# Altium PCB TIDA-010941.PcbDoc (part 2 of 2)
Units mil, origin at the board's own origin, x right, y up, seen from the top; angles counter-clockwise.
Board outline 3700 x 3700 mil, 4 copper layers (Top Layer, POWER, GROUND RETURN, Bottom Layer), stack 60.134 mil thick; 115 components, 62 nets, 289 pads, 271 vias.
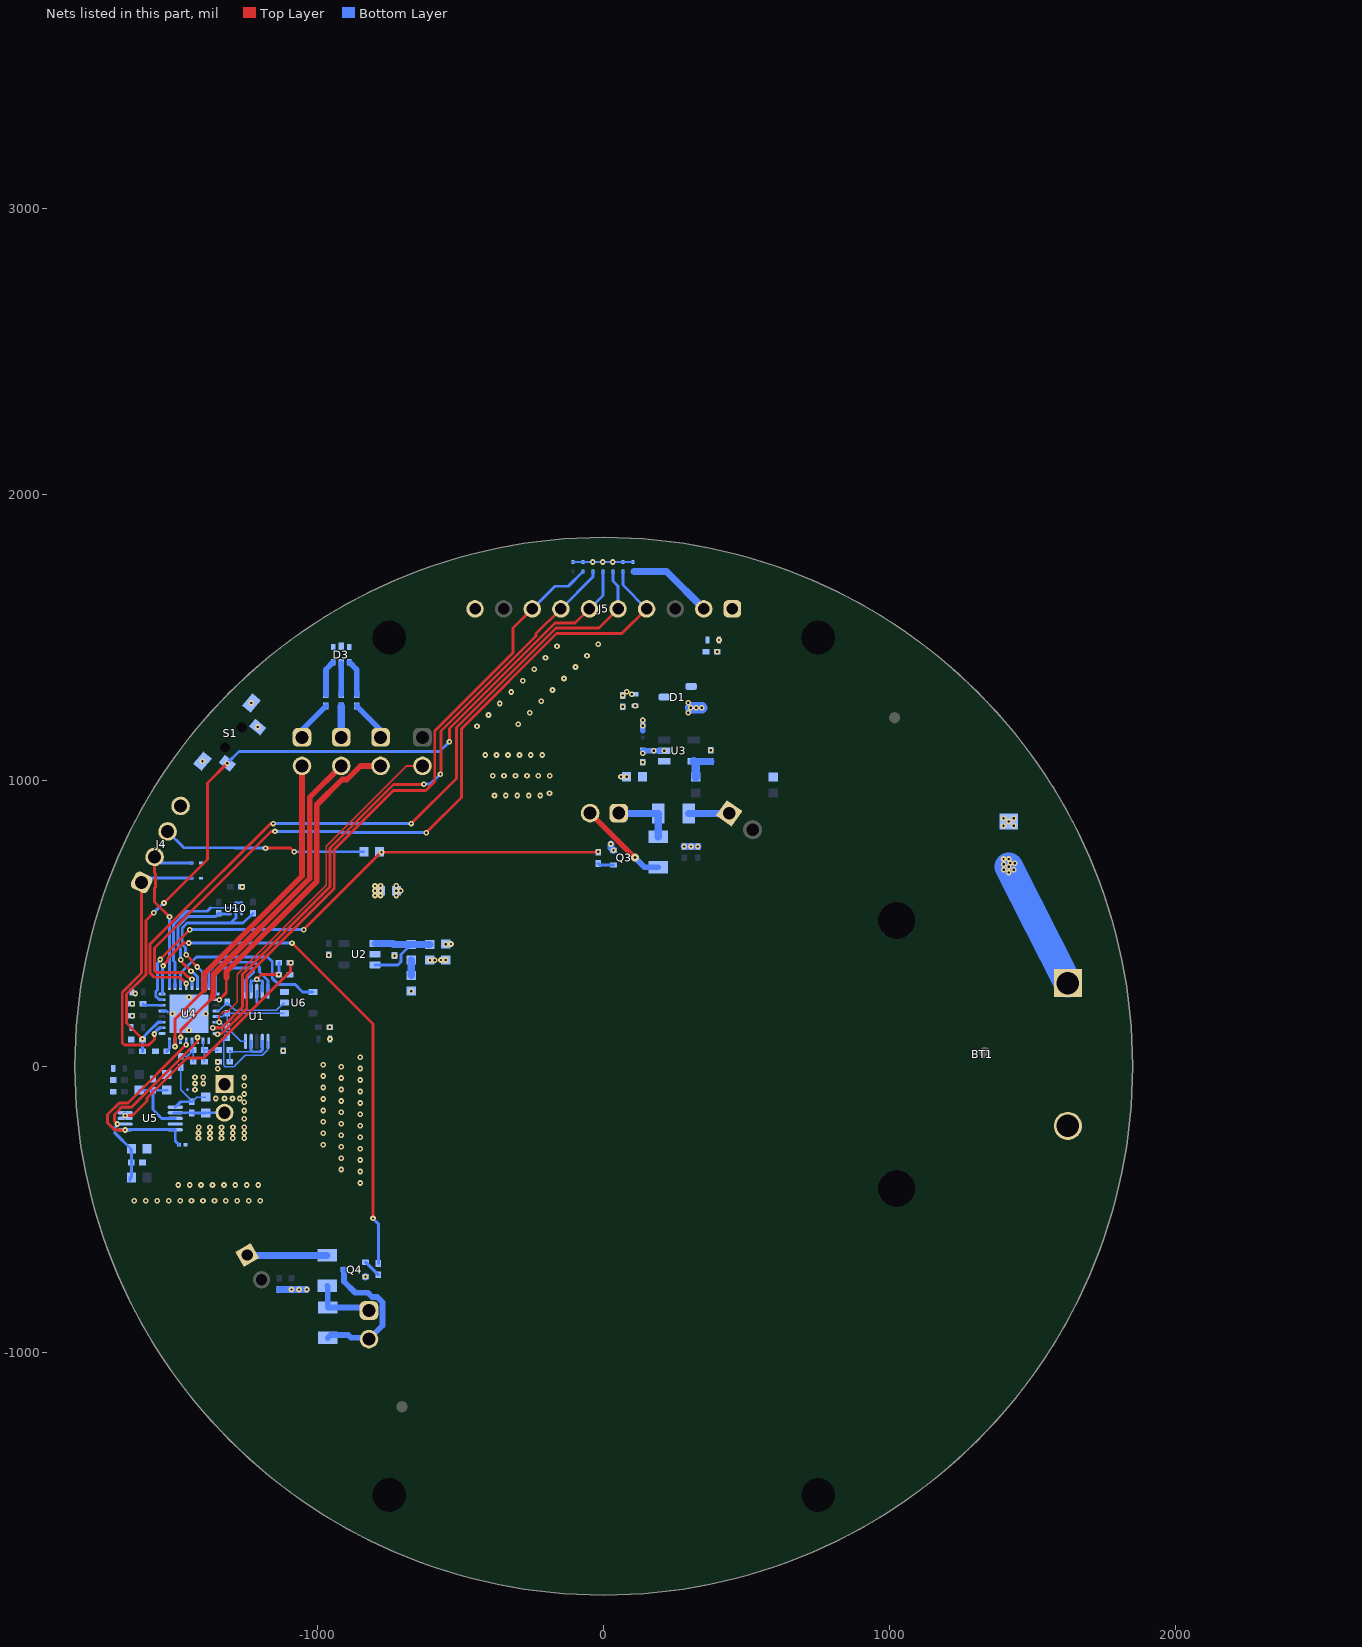
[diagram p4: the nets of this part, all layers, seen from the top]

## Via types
v1: diameter 20, hole 8, Top Layer to Bottom Layer, tented both sides, 215 vias
v2: diameter 19.68, hole 7.87, Top Layer to Bottom Layer, 48 vias
v3: diameter 20, hole 8, Top Layer to Bottom Layer, 7 vias
v4: diameter 28, hole 10, Top Layer to Bottom Layer, tented both sides, 1 vias

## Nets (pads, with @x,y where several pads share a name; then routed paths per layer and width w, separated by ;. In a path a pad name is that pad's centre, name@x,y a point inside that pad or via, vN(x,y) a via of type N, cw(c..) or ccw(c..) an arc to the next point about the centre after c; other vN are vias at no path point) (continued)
GND: C5.2 C8.2 C11.1 C12.2 C13.2 C14.2 C15.2 C16.2 C17.2 C18.2 C19.2 C21.2 C22.2 C24.1 C27.2 C30.2 C34.2 D2.1 D3.1 D3.2 D3.3 D15.2 D16.2 J4.4 J5.10 R8.1 R9.1 R11.2 R16.2 R21.2 S1.1 S1.2 S1.4 U1.3 U2.2 U4.5 U4.25 U4.33 U5.4 U6.3 U10.B1 U10.C1 | length 81.7
  Bottom Layer w10: U4.5@-1545.02,193.57 -1529.51,193.57 -1525.37,189.43 ; -1456.19,-82.19 -1456.19,-81.61 ; U10.B1@-1286.73,572.08 U10.C1@-1267.04,572.08 ; U1.3@-1213.89,262.47 -1213.55,262.12 -1213.55,223.1 -1213.19,222.74
  other v1: -1641.8,-470.14 -1601.8,-470.14 -1561.8,-470.14 -1521.8,-470.14 -1481.8,-470.14 -1441.8,-470.14 -1401.8,-470.14 -1361.8,-470.14 -1321.8,-470.14 -1281.8,-470.14 -1241.8,-470.14 -1201.8,-470.14 -1488.49,-415.02 -1448.49,-415.02 -1408.49,-415.02 -1368.49,-415.02 -1328.49,-415.02 -1288.49,-415.02 -1248.49,-415.02 -1208.49,-415.02 -851.96,-408.16 -851.96,-368.16 -917.96,-361.3 -851.96,-328.16 -917.96,-321.3 -851.96,-288.16 -917.96,-281.3 -981.16,-274.44 -1417.24,-251.62 -1377.24,-251.62 -1337.24,-251.62 -1297.24,-251.62 -1257.24,-251.62 -851.96,-248.16 -917.96,-241.3 -981.16,-234.44 -1417.2,-233.27 -1377.2,-233.27 -1337.2,-233.27 -1297.2,-233.27 -1257.24,-233.27 -1417,-213.03 -1377,-213.03 -1337,-213.03 -1297,-213.03 -1257,-213.03 -851.96,-208.16 -917.96,-201.3 -981.16,-194.44 -1257,-184.07 -851.96,-168.16 -917.96,-161.3 -1257,-155.1 -981.16,-154.44 -851.96,-128.16 -1257,-126.14 -917.96,-121.3 -981.16,-114.44 -1356.71,-112.46 -1326.5,-112.46 -1298.37,-112.46 -1273.35,-112.46 -1257,-97.17 -851.96,-88.16 -1429.84,-82.25 -917.96,-81.3 -981.16,-74.44 -1257,-68.21 -1429.84,-60.54 -1401.16,-60.54 -851.96,-48.16 -917.96,-41.3 -1429.84,-38.89 -1257,-39.24 -1401.32,-38.64 -981.16,-34.44 -1349.79,-8.86 -851.96,-8.16 -917.96,-1.3 -981.16,5.56 -1349.81,15.17 -851.96,31.84 -1121.29,53.89 -957.57,95.52 -958.75,136.04 -1649.11,176.75 -1649.11,218.26 -1638.98,254.22 -962.01,388.05 -800.24,597.53 -780.56,597.53 -800.24,614.26 -780.56,614.26 -1264.91,627.28 -800.24,630.63 -382.48,946.86 -342.48,946.86 -302.48,946.86 -262.48,946.86 -222.48,946.86 -190,955 -388.68,1016.12 -348.68,1016.12 -308.68,1016.12 -268.68,1016.12 -228.68,1016.12 -188.68,1016.12 -1403.31,1066.94 -414.91,1088.78 -374.91,1088.78 -334.91,1088.78 -294.91,1088.78 -254.91,1088.78 -214.91,1088.78 -1210.47,1186.51 -443.39,1188.87 -298.93,1196.32 -403.39,1228.87 -258.93,1236.32 -363.39,1268.87 -1232.49,1270.52 -218.93,1276.32 -323.39,1308.87 -178.93,1316.32 -283.39,1348.87 -138.93,1356.32 -243.39,1388.87 -98.93,1396.32 -203.39,1428.87 -58.93,1436.32 -163.39,1468.87 -18.93,1476.32
  other v2: -1450.54,125.66 -1508.61,183.73 -1450.54,183.73 -1392.47,183.73 -1450.54,241.8
  other v3: -780.56,630.99
GND_5V: BT1.2 C3.1 C4.1 C6.1 C7.1 C23.2 C25.2 C26.2 C31.2 C32.2 C33.1 C35.2 C36.1 C37.2 D6.1 D8.2 D9.2 D10.2 D11.2 D12.2 D13.2 D14.2 J5.1 Q3.2 Q4.2 R16.1 R24.2 R25.1 U3.2 | length 494.3
  Bottom Layer w6: D13.2@-109.36,1763.54 D10.2@-3,1763.54 D14.2@103.36,1763.54
  Bottom Layer w20: C26.2@136.04,1102.81 137.2,1103.97 v1(211.91,1103.97) ; R24.2@136.04,1174.07 v1(136.04,1210)
  Bottom Layer w25: C6.1@-1134.48,-780.69 v1(-1092.09,-780.69) v1(-1039.26,-780.69) ; Q4.2@-833.49,-736.52 v2(-833.49,-736.34) ; v1(24.98,777.56) 24.98,764.3 v1(34.17,755.11) ; v1(281.32,768.89) v1(328.99,768.89)
  other v1: -1065.67,-780.69 -673.28,262.83 -731.95,387.01 -552.59,426.93 -533.91,427.43 -725.44,597.53 -725.44,614.26 -709.69,614.26 -725.44,630.99 305.16,768.89 1398.61,841.68 1434.53,841.68 1417,856.33 1398.61,867.55 1434.53,867.55 60.69,1013.08 80.38,1013.08 136.04,1094.94 174.55,1103.97 374.65,1105.18 136.04,1191.35 66.57,1257.58 109.96,1261.26 397.43,1450 403.21,1491 -38.01,1763.54 -3,1763.73 32.01,1763.73
HDC_INT: U4.10 U10.C2 | length 490.6
  Bottom Layer w5: -1374.52,554.65 -1288.98,554.65 U10.C2@-1267.04,532.71
  Bottom Layer w10: U4.10@-1499.75,278.22 -1499.75,364.38 -1504.43,369.07 -1504.43,496.19 -1458.54,542.09 -1387.08,542.09 -1374.52,554.65
HDC_SCL: R12.2 U4.15 U10.B2 | length 545
  Top Layer w10: v2(-1460.71,390.41) -1440.72,370.42 -1440.72,366 v2(-1421.82,347.11)
  Bottom Layer w10: v2(-1460.71,390.41) -1462.57,392.27 -1462.57,414.56 -1474.43,426.43 -1474.43,483.76 -1457.66,500.54 -1305.69,500.54 ; v2(-1421.82,347.11) -1420.84,347.11 -1401.32,327.59 U4.15@-1401.32,278.22 ; U10.B2@-1286.73,532.71 -1286.73,519.5 -1305.69,500.54 ; R12.2@-1227.03,534.81 -1261.31,500.54 -1305.69,500.54
HDC_SDA: R13.2 U4.14 U10.A2 | length 444.9
  Top Layer w10: v2(-1480,372.7) -1480,368.89 v2(-1443.65,332.54)
  Bottom Layer w10: v2(-1480,372.7) -1480.56,373.25 -1480.56,411.34 -1489.43,420.21 -1489.43,489.98 -1456.15,523.26 -1358.12,523.26 R13.2@-1346.42,534.96 -1344.16,532.71 U10.A2@-1306.41,532.71 ; v2(-1443.65,332.54) -1441.79,330.69 -1438.91,330.69 -1420.38,312.15 -1420.38,295.72 -1420.93,295.17 -1420.93,278.3 U4.14@-1421.01,278.22
I_TIA_IN: C1.2 D2.2 R2.2 U5.2 | length 179.3
  Bottom Layer w5: R2.2@-1392.96,-163.36 R2.2@-1392.28,-162.67 R2.2@-1391.33,-161.72
  Bottom Layer w10: U5.2@-1504.09,-162.77 -1441.26,-162.77 C1.2@-1440.67,-163.36 R2.2@-1392.96,-163.36 ; R2.2@-1392.07,-162.46 D2.2@-1326.5,-162.46
INT_RST_T1C0: U4.11 U6.4 | length 619.6
  Bottom Layer w10: U4.11@-1480.06,278.22 -1480.06,284.95 -1480.22,285.11 -1480.22,326.24 -1423.96,382.5 -1175.57,382.5 -1159.37,366.29 -1159.37,307.8 -1138.15,286.58 -1079.65,286.58 -1053.22,260.14 U6.4@-1016.95,260.14
LED_BLUE_MOD_T2C1: R23.2 U4.8 | length 1834.6
  Top Layer w10: v2(-1541.3,351.06) -1541.3,353.62 -1525.01,369.9 -1525.01,376.97 -1470.63,431.35 v2(-1451.3,431.35) ; v2(-1090.41,430.86) -973.12,313.58 -972.81,313.58 -806.91,147.68 v2(-806.91,-532.2)
  Bottom Layer w10: U4.8@-1543.15,252.71 -1543.15,349.2 v2(-1541.3,351.06) ; v2(-1451.3,431.35) v2@-1090.88,431.33 ; v2(-806.91,-532.2) -788.49,-550.62 R23.2@-788.49,-690.04
LED_DEMOD_T0_N: U1.1 U4.17 | length 306.3
  Bottom Layer w10: U4.17@-1356.05,252.63 -1357.83,254.41 -1357.83,328.07 -1342.18,343.72 -1229.96,343.72 -1224.11,337.86 -1224.11,329.57 -1252.92,300.76 -1252.92,262.82 U1.1@-1253.26,262.47
LED_DEMOD_T0_P: U1.5 U4.16 | length 348
  Bottom Layer w10: U4.16@-1381.64,278.22 -1381.64,332.54 -1350.46,363.72 -1221.68,363.72 -1204.11,346.14 -1204.11,329.27 -1174.87,300.03 -1174.87,262.82 U1.5@-1174.52,262.47
LED_IR_MOD_T2C0: R22.2 R26.2 U4.7 | length 1854.6
  Top Layer w10: v2(-1551.7,373.63) v2@-1450.25,475.08 ; v2(-1049.7,477.62) -778.83,748.48 v3(-777.22,748.48) -21.44,748.48 v2(-19.49,750.43)
  Bottom Layer w10: v2(-1551.7,373.63) -1551.7,371.01 -1561.14,361.57 -1561.14,266.23 -1566.84,260.54 -1566.84,244.72 -1555.06,232.94 U4.7@-1545.02,232.94 ; v2(-1447.71,477.62) -1447.16,478.16 -1050.24,478.16 v2(-1049.7,477.62) ; R26.2@-784.11,750.13 -778.87,750.13 v3(-777.22,748.48)
NetC27_1: C27.1 R5.1 R8.2 U5.3 | length 255.2
  Bottom Layer w10: R5.1@-1624.93,-83.84 -1577.03,-83.84 C27.1@-1576.54,-84.33 ; R8.2@-1527.91,-83.84 -1576.04,-83.84 C27.1@-1576.54,-84.33 ; U5.3@-1498.83,-182.35 -1545.91,-182.35 -1576.54,-151.72 C27.1@-1576.54,-84.33
NetC38_1: C38.1 R25.2 | length 53.3
  Bottom Layer w25: R25.2@-673.28,317.95 C38.1@-673.28,371.27
NetD3_4: D3.4 R20.1 | length 123.7
  Bottom Layer w20: R20.1@-971.85,1299.71 -971.85,1387.75 D3.4@-946.65,1412.94
NetD3_5: D3.5 R18.2 | length 110.3
  Bottom Layer w20: R18.2@-918.11,1299.71 D3.5@-918.11,1409.99
NetD3_6: D3.6 R19.2 | length 123.7
  Bottom Layer w20: D3.6@-889.57,1412.94 -864.37,1387.75 R19.2@-864.37,1299.71
NetD4_1: D4.1 R6.1 | length 142.1
  Bottom Layer w25: R6.1@297.1,884.57 R6.1@296.95,884.42 438.39,884.42 D4.1@438.68,884.72
NetD5_1: D5.1 R10.1 | length 280.2
  Bottom Layer w25: D5.1@-1246.93,-660.1 -1245.33,-661.7 R10.1@-967.43,-661.7
NetJ1_1: J1.1 R19.1 | length 144.3
  Bottom Layer w20: R19.1@-864.37,1260.34 -780.72,1176.7 J1.1@-780.72,1150.65
NetJ2_1: J2.1 R18.1 | length 109.7
  Bottom Layer w25: J2.1@-918.11,1150.65 R18.1@-918.11,1260.34
NetJ3_1: J3.1 R20.2 | length 144.3
  Bottom Layer w20: J3.1@-1055.5,1150.65 -1055.5,1176.7 R20.2@-971.85,1260.34
NetJ4_3: J4.3 R26.1 | length 716
  Top Layer w10: v3(-1183.47,762.9) -1095.67,762.9 v3(-1082.9,750.13)
  Bottom Layer w10: J4.3@-1525.74,821.4 -1468.6,764.26 -1289.16,764.26 -1288.9,764 -1184.57,764 v3(-1183.47,762.9) ; v3(-1082.9,750.13) R26.1@-839.23,750.13
NetJ7_1: J7.1 R6.2 R27.1 | length 220.8
  Bottom Layer w25: J7.1@52.47,885.42 53.47,884.42 R6.2@190.65,884.42 190.65,802.52 R27.1@190.85,802.33
NetJ7_2: J7.2 Q3.3 R27.2 | length 319.6
  Top Layer w20: J7.2@-45.07,885.42 J7.2@-47.53,885.42 107.29,730.6 v4(109.75,730.6)
  Bottom Layer w20: Q3.3@108.98,729.52 142.47,696.03 R27.2@190.85,696.03
NetJ8_1: J8.1 R10.2 R28.1 | length 225.1
  Bottom Layer w20: R10.2@-967.43,-768 -965.07,-770.36 R28.1@-965.07,-843.85 -831.78,-843.85 J8.1@-821.22,-854.41
NetJ8_2: J8.2 Q4.3 R28.2 | length 509.7
  Bottom Layer w20: R28.2@-965.07,-950.15 -954.84,-939.93 -893.7,-939.93 -883.7,-949.93 -825.7,-949.93 J8.2@-821.22,-954.41 -773.74,-906.93 -773.74,-825.23 -792.04,-806.93 -810.07,-806.93 -824.55,-792.45 -869.17,-792.45 -908.29,-753.33 Q4.3@-908.29,-710.93
NetQ3_1: Q3.1 R22.1 | length 55.8
  Bottom Layer w10: R22.1@-19.49,709.11 -14.31,703.93 Q3.1@34.17,703.93
NetQ4_1: Q4.1 R23.1 | length 63.2
  Bottom Layer w10: Q4.1@-833.49,-685.34 -832.56,-685.34 R23.1@-788.49,-729.41
NetR4_2: R4.2 U1.6 | length 314
  Bottom Layer w5: R4.2@-1316.76,100.53 -1328.76,88.52 -1328.76,69.85 -1328.53,69.62 -1328.53,3.66 -1328.16,3.29 -1327.78,3.29 -1327.78,2.22 -1323.39,-2.18 -1293.55,-2.18 -1289.16,2.22 -1289.16,3.47 -1254.43,38.2 -1194.15,38.2 -1174.52,57.83 U1.6@-1174.52,87.27
NetR29_2: R29.2 U5.8 U5.9 | length 845.4
  Top Layer w10: v2(-1674.03,-172.51) -1648.36,-172.51 -1597.37,-121.53 -1597.37,-110.64 -1457.79,28.95 -1399.35,28.95 -1095.09,333.21 v2(-1095.09,362.14)
  Bottom Layer w10: U5.8@-1674.03,-182.35 v2(-1674.03,-172.51) U5.9@-1674.03,-162.67 ; R29.2@-1097.03,362.14 v2(-1095.09,362.14)
OPA0_IN0-: C2.2 C10.2 R1.2 U4.28 | length 126.5
  Bottom Layer w5: C10.2@-1479.51,35.02 -1457.69,35.02 R1.2@-1436.04,56.67 -1440.69,61.33 U4.28@-1440.69,89.24 ; C2.2@-1436.04,15.17 R1.2@-1436.04,54.7
OPA0_OUT: C2.1 R1.1 R3.2 U4.26 | length 124.8
  Bottom Layer w5: U4.26@-1401.32,89.24 -1401.32,61.33 R1.1@-1396.67,56.67 ; C2.1@-1396.67,15.17 R1.1@-1396.67,56.67 ; R3.2@-1347.84,56.67 R1.1@-1396.67,56.67
OPA1_IN0+: J6.2 U1.10 U4.22 | length 1373.2
  Top Layer w6: v2(-1344.58,154.2) -1345.67,155.3 -1345.67,176.05 -1330.89,190.83 -1316.15,190.83 -1282.14,224.84 -1282.14,321.69 -970.72,633.12 -970.72,769.38 -689.45,1050.65 J6.2@-634,1050.65
  Bottom Layer w5: v2@-1342.02,154.2 -1334.1,146.28 -1334.1,124.98 -1329.7,120.59 -1303.81,120.59 -1270.49,87.27 U1.10@-1253.26,87.27
  Bottom Layer w10: U4.22@-1356.05,154.2 v2(-1344.58,154.2)
OPA1_IN0-: C9.1 R4.1 U4.21 U6.1 | length 282.2
  Bottom Layer w5: U4.21@-1356.05,173.89 -1334.93,173.89 C9.1@-1323.48,185.34 ; R4.1@-1316.76,139.9 C9.1@-1316.76,185.34 U6.1@-1117.35,185.34
OPA1_OUT: C9.2 U4.20 U6.2 | length 273.5
  Bottom Layer w5: U4.20@-1356.05,193.57 -1345.92,193.57 -1316.76,222.74 -1289.35,195.34 -1144.75,195.34 U6.2@-1117.35,222.74
PA19_SWDIO: D11.1 J5.7 U4.23 | length 2262
  Top Layer w10: v2(-1367.78,134.49) -1367.65,134.36 -1336.36,134.36 -1263.58,207.14 -1263.58,321.87 -957.72,627.73 -957.72,764 -735.62,986.09 v2(-629.07,986.09) ; v2(-571.37,1021.76) -569.32,1023.81 -569.32,1172.9 -236.77,1505.46 -236.77,1513.23 J5.7@-150,1600
  Bottom Layer w10: v2(-1367.78,134.49) -1369.83,132.44 -1369.83,129.75 -1360.81,129.75 U4.23@-1356.05,134.52 ; v2(-629.07,986.09) -627.22,987.95 -605.19,987.95 v2(-571.37,1021.76) ; J5.7@-150,1600 -38.01,1711.99 D11.1@-38.01,1730.46
PA20_SWCLK: D12.1 J5.8 U4.24 | length 2256.7
  Top Layer w10: v2(-1351.24,112.37) -1349.38,114.23 -1335.28,114.23 -1248.58,200.93 -1248.58,315.66 -942.72,621.52 -942.72,757.79 -736.24,964.26 -622.84,964.26 -591.21,995.89 -591.21,1172.22 -317,1446.43 -317,1533 J5.8@-250,1600
  Bottom Layer w10: U4.24@-1356.05,114.83 -1351.32,114.83 -1351.24,114.75 v2(-1351.24,112.37) ; J5.8@-250,1600 -170.77,1679.23 -124.26,1679.23 D12.1@-73.03,1730.46
PA.0: U4.1
PA.1: D15.1 J4.1 U4.2 | length 952.4
  Top Layer w10: J4.1@-1616.54,643.2 -1616.54,326.16 -1684.11,258.59 -1684.11,81.43 -1676.57,73.9 -1591.76,73.9 -1571.68,93.98 v2(-1571.68,112.82)
  Bottom Layer w10: J4.1@-1616.54,643.2 -1601.79,657.94 D15.1@-1441.32,657.94 ; v2(-1571.68,112.82) -1566.84,117.66 -1566.84,122.74 -1559.82,129.75 -1554.74,129.75 -1549.98,134.52 U4.2@-1545.02,134.52
PA.5: D16.1 J4.2 U4.9 | length 616.5
  Top Layer w10: J4.2@-1571.14,732.3 -1571.14,675.78 -1568.46,673.09 -1568.46,625.22 -1571.14,622.53 -1571.14,574.65 v3(-1519.25,522.76)
  Bottom Layer w10: J4.2@-1571.14,732.3 -1549.94,711.1 D16.1@-1441.32,711.1 ; U4.9@-1519.43,278.22 -1519.43,522.58 v3(-1519.25,522.76)
PA.14: J1.2 U4.18 | length 1109.4
  Top Layer w10: v2(-1344.58,232.94) -1320.51,257.01 -1320.51,309.26 -1319.28,310.5
  Top Layer w20: -1319.28,310.5 -1319.28,331.23 -1003.72,646.79 -1003.72,914.56 -915.1,1003.17 -898.44,1003.17 -850.96,1050.65 J1.2@-780.72,1050.65
  Bottom Layer w6: v2@-1345.68,239.71 -1344.58,238.61 v2(-1344.58,232.94)
PA.26: J2.2 U4.30 | length 1194.9
  Top Layer w10: v2(-1480.04,100.97) -1479.43,101.58 -1479.43,125.82 -1427.58,177.67 -1427.58,181.25 -1370.73,238.1 -1369.42,238.1
  Top Layer w20: -1369.42,238.1 -1369.42,243.23 -1366.02,246.64 -1366.02,319.84 -1028.72,657.14 -1028.72,940.04 J2.2@-918.11,1050.65
  Bottom Layer w10: U4.30@-1480.05,89.26 v2(-1480.04,100.97)
PA.27: J3.2 U4.31 | length 1188
  Top Layer w10: -1499.88,109.19 -1499.88,98.84 -1502,96.72 -1499.51,94.23 v2(-1499.51,69) ; -1499.75,109.32 -1499.75,164.53 -1397.29,266.98 -1396.98,266.98
  Top Layer w20: -1396.98,266.98 -1396.98,324.24 -1055.5,665.72 J3.2@-1055.5,1050.65
  Bottom Layer w10: U4.31@-1499.75,89.24 U4.31@-1499.75,89.24 -1499.67,69.16 v2(-1499.51,69)
R\S\T\: C34.1 D10.1 J5.6 R17.2 S1.3 U4.3 | length 2945.2
  Top Layer w10: v2(-1613.57,95.26) -1669.11,150.8 -1669.11,252.37 -1601.54,319.94 -1601.54,509.95 -1574.71,536.78 v3(-1573.89,536.78) ; v3(-1538.22,571.14) -1385.58,723.78 -1385.58,991.02 v2(-1316.76,1059.84) ; v2(-539.8,1134.88) -539.8,1181.21 -171.01,1550 -100,1550 J5.6@-50,1600
  Bottom Layer w10: R17.2@-1613.57,52.23 -1613.57,89.8 -1611.6,91.77 -1611.6,100.96 -1591.3,121.26 ; -1590.23,122.33 -1558.36,154.2 U4.3@-1545.02,154.2 ; v3(-1573.89,536.78) -1539.53,571.14 v3(-1538.22,571.14) ; v2(-1316.76,1059.84) -1275.95,1100.65 -574.03,1100.65 v2(-539.8,1134.88) ; J5.6@-54.4,1604.4 J5.6@-50,1600 -3,1647 D10.1@-3,1730.46
ROSC: R11.1 U4.6 | length 69.1
  Bottom Layer w10: R11.1@-1612.04,218.26 -1607.04,213.26 U4.6@-1545.02,213.26
S\H\D\N\_\T\I\A\: R21.1 U4.29 U5.5 U5.6 | length 725.2
  Top Layer w10: v2(-1674.25,-222.79) -1710.6,-222.66 -1735.76,-197.5 -1735.76,-169.32 -1694.44,-128 -1664.01,-128 v2(-1460.84,75.17)
  Bottom Layer w6: v2(-1460.84,75.17) -1460.38,75.63 U4.29@-1460.38,89.24
  Bottom Layer w10: v2(-1674.25,-222.79) -1674.25,-221.94 U5.6@-1674.03,-221.72 U5.5@-1498.83,-221.72 -1498.83,-261.07 R21.1@-1485.46,-274.44
TARGET_RXD: D8.1 J5.4 U4.13 | length 2764.9
  Top Layer w10: v2(-1440.22,303.94) -1442.84,303.94 -1451.6,312.7 -1454.83,312.7 -1470.2,328.07 -1565.68,328.07 -1571.54,333.93 -1571.54,413.79 -1163.93,821.4 v2(-1149.74,821.4) ; v2(-620.67,817.19) -497.86,940 -497.86,1180.72 -165.35,1513.23 63.23,1513.23 J5.4@150,1600
  Bottom Layer w10: U4.13@-1440.62,285.03 -1440.54,285.11 -1440.54,303.62 v2(-1440.22,303.94) ; v2(-1149.74,821.4) -922.87,821.4 -918.67,817.19 v2(-620.67,817.19) ; D8.1@67.03,1730.46 67.03,1682.97 J5.4@150,1600
TARGET_TXD: D9.1 J5.5 U4.12 | length 2607.3
  Top Layer w10: v2(-1460.38,289.69) -1481.96,311.27 -1572.44,311.27 -1586.54,325.37 -1586.54,427.32 -1511.1,502.76 -1510.97,502.76 -1499.25,514.48 -1499.25,514.61 -1165.05,848.82 v2(-1156.07,848.82) ; v2(-673.28,848.82) -515,1007.1 -515,1184.8 -166.8,1533 -17,1533 J5.5@50,1600
  Bottom Layer w10: v2(-1156.07,848.82) v2(-673.28,848.82) ; D9.1@32.01,1730.46 32.01,1697.23 50,1679.23 J5.5@50,1600
VBAT_9V0: BT1.1 D1.2 D6.2 | length 494.2
  Bottom Layer w40: v1(304.23,1253.93) v1(342.58,1253.93)
  Bottom Layer w100: v1(1417,697.67) BT1.1@1623.43,291.18
  other v1: 1417,677.79 1399.47,687.73 1434.53,687.72 1399.47,706.97 1437.87,709.87 1421.61,710.95 1398.61,725.23 1417,725.23 296,1236.18 323.4,1253.93 296,1271.71
VCORE: C21.1 U4.32 | length 40.9
  Bottom Layer w10: C21.1@-1528.76,52.23 -1519.43,61.56 U4.32@-1519.43,89.24
VeREF+: C12.1 R7.1 R9.2 U4.27 U5.7 | length 686.6
  Top Layer w10: v2(-1701.25,-202.04) -1710.91,-192.38 -1710.91,-168.87 -1685.04,-143 -1650.95,-143 -1421.01,86.94 v2(-1421.01,100.71)
  Bottom Layer w10: U5.7@-1699.38,-203.91 -1710.6,-215.14 -1710.6,-232.31 -1652.18,-290.74 -1655.56,-294.12 -1652.18,-297.5 R7.1@-1652.18,-389 ; R7.1@-1657.6,-399.76 R7.1@-1657.6,-389 ; U4.27@-1421.01,89.24 -1421.31,88.94 -1421.31,100.41 v2(-1421.01,100.71)
VIN_LDO: C26.1 C31.1 C32.1 C33.2 C37.1 D1.3 L1.2 U3.1
  other v1: -607.88,370.77 -591.14,371.27 -569.32,371.82 -552.59,371.32 136.04,1063.44 66.57,1296.95 97.96,1301.26 80.35,1309.62
VIN_LDO33: C23.1 C38.2 L1.1 U2.1 U2.3 | length 365.2
  Bottom Layer w10: U2.3@-800.39,354.58 -720.15,354.58 -708.93,365.81 -708.93,390.74 C38.2@-673.28,426.38
  Bottom Layer w25: U2.1@-800.39,429.39 -734.95,429.39 C23.1@-731.95,426.38 C38.2@-673.28,426.38 L1.1@-607.88,426.38
VLP_5V0: C35.1 C36.2 D1.1 D14.1 J5.2 R14.2 | length 297.1
  Bottom Layer w25: 106.95,1730.46 219.54,1730.46 J5.2@350,1600
VLPF: C11.2 R3.1 U1.7 U1.9 | length 229.2
  Bottom Layer w5: C11.2@-1308.47,15.17 -1308.72,15.41 -1308.47,15.66 R3.1@-1308.47,56.67 -1302.5,50.7 -1228.98,50.7
  Bottom Layer w10: U1.9@-1233.58,87.27 -1233.58,55.3 -1228.98,50.7 -1201.5,50.7 -1194.21,57.99 U1.7@-1194.21,87.27
VOUT_LDO50: C25.1 R15.2 U3.5 | length 118.9
  Bottom Layer w25: U3.5@314.28,1066.57 373.89,1066.57 C25.1@374.65,1065.81
  Bottom Layer w30: U3.5@314.28,1066.57 321.93,1058.92 R15.2@321.93,1011.56
VREF_LPF: C19.1 R29.1 U1.2 U1.4 | length 247.3
  Top Layer w10: v2(-1213.69,303.89) -1196.94,320.63 v2(-1136.4,320.63)
  Bottom Layer w10: U1.2@-1233.58,262.47 -1233.58,298.89 -1220.64,298.89 -1220.48,299.05 -1213.89,299.05 v2@-1213.74,299.2 ; U1.4@-1194.21,262.47 -1194.21,298.16 -1194.94,298.89 -1207.15,298.89 -1207.31,299.05 -1213.74,299.05 v2@-1213.74,299.2 ; v2(-1136.4,320.63) R29.1@-1136.4,362.14 ; v2@-1213.74,299.2 -1213.74,303.84 v2(-1213.69,303.89) -1213.69,299.25 v2@-1213.74,299.2
VTIA_OUT: C1.1 C10.1 R2.1 U5.1 | length 257
  Bottom Layer w5: C10.1@-1479.51,-4.35 -1479.51,-82.33 -1448.01,-113.83 -1448.01,-116.64 C1.1@-1440.67,-123.99 -1424.23,-107.55 R2.1@-1392.28,-107.55
  Bottom Layer w10: U5.1@-1498.83,-142.98 -1479.83,-123.99 C1.1@-1440.67,-123.99
pads on no net: BT1.MH1 BT1.MH2 FID1.1 FID2.1 FID3.1 H1. H2. H3. H4. J5.3 LBL1.0 S1. U2.4 U3.4

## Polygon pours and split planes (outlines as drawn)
GND on POWER "GND_GUARDRING" (solid, pour order 44): -1588.95,-97.94 -1540.99,-97.94 -1544.82,-97.94 -1544.82,-86.2 -1543.49,-84.87 -1543.49,-38.64 -1538.22,-33.36 -1516.16,-33.36 -1515.19,-32.39 -1509.91,-32.39 -1484.01,-6.49 -1459.66,-6.49 -1457.85,-4.68 -1374.86,-4.68 -1374.86,31.62 -1369.65,36.83 -1334.53,36.83 -1332.71,35.01 -1330.28,35.01 -1330.28,-4.68 -1286.66,-4.68 -1286.66,98.12 -1282.14,102.64 -1257.91,102.64 -1257.9,51.01 -1240.03,33.14 -1240.03,-36.31 -1240.03,-84.87 -1240.03,-148.3 -1240.03,-326.96 -1588.95,-326.96
5V0 on POWER "POWER-5V0" (solid, remove dead copper, pour order 59): -1897,-1989 858,-1989 858,973.8 267.91,973.8 267.91,57 -745.73,57 -745.73,-560 -1897,-560
VBAT_9V0 on POWER "POWER_VBAT_9V0_P058" (solid, remove dead copper, pour order 58): -554,1821 -565.17,1809.83 -565.17,1677.41 267.31,1677.41 267.31,993.94 870.06,993.94 882,982 880.53,980.53 880.53,-1813 893,-1813 1814,-892 1814,1788 1781,1821
VIN_LDO on POWER "POWER_VIN_LDO_P043" (solid, remove dead copper, pour order 43): 41.14,1340.19 250,1340.19 250,70 -745.73,70 -745.73,693.36 -34.36,693.36 -34.36,1099.25 41.14,1099.25 162.95,1099.25 162.95,1155.94 41.14,1155.94
3V3 on POWER "POWER_3V3_P053" (solid, pour order 53): -1508.68,-538.49 -761.64,-538.49 -761.64,712.1 -49.52,712.1 -49.52,1111.49 155.88,1111.49 155.88,1153.87 28.42,1153.87 28.42,1353.38 213.32,1353.38 213.32,1665 -676.46,1665 -744.22,1624.06 -788,1606.39 -883.59,1567.82 -976.3,1516.23 -1112.91,1412.99 -1210.08,1330.1 -1735.76,804.43 -1735.76,523.26 -1777.02,482 -1778.02,483 -1780.02,483 -1780.02,474.77 -1828.02,426.77 -1828.02,-319 -1710.64,-538.49
GND_5V on GROUND RETURN "GROUND_RETURN_GND_5V_P040" (solid, remove dead copper, pour order 40): -620.67,1667 215.95,1667 215.95,1340.19 41.14,1340.19 41.14,1155.94 162.95,1155.94 162.95,1099.29 -34.36,1099.29 -34.36,693.36 -748.24,693.36 -748.24,-560 -1699.95,-560 -1950,-560 -875.43,-2068 565.85,-2068 1808,-914 1808,1794 1794,1808 -607,1808 -620.67,1733 -677.23,1667.74
GND on GROUND RETURN "GROUND_RETURN_GND_P055" (solid, pour order 55): -1508.68,-538.49 -761.64,-538.49 -761.64,712.1 -49.52,712.1 -49.52,1111.49 155.88,1111.49 155.88,1153.87 28.42,1153.87 28.42,1353.38 213.32,1353.38 213.32,1665 -676.46,1665 -744.22,1624.06 -788,1606.39 -883.59,1567.82 -976.3,1516.23 -1112.91,1412.99 -1210.08,1330.1 -1735.76,804.43 -1735.76,523.26 -1777.02,482 -1778.02,483 -1780.02,483 -1780.02,474.77 -1828.02,426.77 -1828.02,-319 -1710.64,-538.49
GND on GROUND RETURN "GND_GUARDRING" (solid, pour order 51): -1588.95,-97.94 -1540.99,-97.94 -1544.82,-97.94 -1544.82,-86.2 -1543.49,-84.87 -1543.49,-38.64 -1538.22,-33.36 -1516.16,-33.36 -1515.19,-32.39 -1509.91,-32.39 -1484.01,-6.49 -1459.66,-6.49 -1457.85,-4.68 -1374.86,-4.68 -1374.86,31.62 -1369.65,36.83 -1334.53,36.83 -1332.71,35.01 -1330.28,35.01 -1330.28,-4.68 -1286.66,-4.68 -1286.66,98.12 -1282.14,102.64 -1257.91,102.64 -1257.9,51.01 -1240.03,33.14 -1240.03,-36.31 -1240.03,-84.87 -1240.03,-148.3 -1240.03,-326.96 -1517.4,-326.96 -1588.95,-326.96
5V0 on Bottom Layer "Bottom Layer-5V0" (solid, remove dead copper, pour order 60): -1793,-1854 858,-1854 858,974.53 250,974.53 250,57 -745.73,57 -745.73,-560 -1793,-560
VIN_LDO on Bottom Layer "BOTTOM_LAYER_VIN_LDO_P057" (solid, remove dead copper, pour order 57): 40.96,1340.74 266.56,1340.74 266.56,70.56 -745.92,70.56 -745.92,693.92 -34.55,693.92 -34.55,1099.81 40.96,1099.81 162.77,1099.81 162.77,1155.94 40.96,1155.94
GND on Bottom Layer "BOTTOM_LAYER_GND_P056" (solid, pour order 56): -1508.68,-538.49 -761.64,-538.49 -761.64,712.1 -49.52,712.1 -49.52,1111.49 155.88,1111.49 155.88,1153.87 28.42,1153.87 28.42,1353.38 213.32,1353.38 213.32,1665 -1002.67,1665 -1778.02,1003.57 -1778.02,483 -1780.02,483 -1780.02,474.77 -1828.02,426.77 -1828.02,-519.6 -1817.92,-538.49
GND on Bottom Layer "GND_GUARDRING" (solid, pour order 32): -1588.95,-97.94 -1540.99,-97.94 -1544.82,-97.94 -1544.82,-86.2 -1543.49,-84.87 -1543.49,-38.64 -1538.22,-33.36 -1516.16,-33.36 -1515.19,-32.39 -1509.91,-32.39 -1484.01,-6.49 -1459.66,-6.49 -1457.85,-4.68 -1374.86,-4.68 -1374.86,31.62 -1369.65,36.83 -1334.53,36.83 -1332.71,35.01 -1330.28,35.01 -1330.28,-4.68 -1286.66,-4.68 -1286.66,98.12 -1282.14,102.64 -1257.91,102.64 -1257.9,51.01 -1240.03,33.14 -1240.03,-36.31 -1240.03,-84.87 -1240.03,-148.3 -1240.03,-326.96 -1517.4,-326.96 -1588.95,-326.96
VLP_5V0 on Bottom Layer "VLP_5V0_bot" (solid, remove dead copper, pour order 28): 857,984 267.31,984 267.31,1000 267.31,1681.09 -777.24,1681.09 -777.24,1795.14 857.1,1795.14 857,1792.98
GND on Top Layer "GND_GUARDRING" (solid, pour order 52): -1588.95,-97.94 -1540.99,-97.94 -1544.82,-97.94 -1544.82,-86.2 -1543.49,-84.87 -1543.49,-38.64 -1538.22,-33.36 -1516.16,-33.36 -1515.19,-32.39 -1509.91,-32.39 -1484.01,-6.49 -1459.66,-6.49 -1457.85,-4.68 -1374.86,-4.68 -1374.86,31.62 -1369.65,36.83 -1334.53,36.83 -1332.71,35.01 -1330.28,35.01 -1330.28,-4.68 -1286.66,-4.68 -1286.66,98.12 -1282.14,102.64 -1257.91,102.64 -1257.9,51.01 -1240.03,33.14 -1240.03,-36.31 -1240.03,-84.87 -1240.03,-148.3 -1240.03,-326.96 -1517.4,-326.96 -1588.95,-326.96

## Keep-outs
Keep-Out Layer:
  text ".Layer_Name" at -1161.91,-2932.68 h60

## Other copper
Top Layer:
  pour cut-out: -1467.9,-146.76 -1435.9,-146.76 -1415.9,-146.76 -1414.08,-142.58 -1357.64,-142.58 -1340.94,-125.89 -1337.43,-125.89 -1314.23,-125.89 -1310.71,-125.89 -1299.69,-136.9 -1291.82,-148.3 -1289.33,-150.78 -1289.33,-177.5 -1291.82,-179.99 -1310.71,-198.88 -1314.23,-198.88 -1337.43,-198.88 -1340.94,-198.88 -1355.74,-184.08 -1370.61,-184.08 -1414.08,-184.08 -1417.33,-180.83 -1439.68,-180.83 -1455.58,-180.83 -1470.55,-180.83 -1475.02,-185.3 -1475.02,-188.26 -1477.11,-190.36 -1480.07,-190.36 -1501.87,-190.36 -1503.96,-188.26 -1504.73,-188.26 -1504.73,-187.49 -1506.28,-185.95 -1506.28,-143.38 -1506.28,-140.42 -1503.18,-137.32 -1500.22,-137.32 -1499.68,-136.78 -1499.14,-137.32 -1477.34,-137.32 -1472.93,-141.73
POWER:
  pour cut-out: -1467.9,-146.76 -1435.9,-146.76 -1415.9,-146.76 -1414.08,-142.58 -1357.64,-142.58 -1340.94,-125.89 -1337.43,-125.89 -1314.23,-125.89 -1310.71,-125.89 -1299.69,-136.9 -1291.82,-148.3 -1289.33,-150.78 -1289.33,-177.5 -1291.82,-179.99 -1310.71,-198.88 -1314.23,-198.88 -1337.43,-198.88 -1340.94,-198.88 -1355.74,-184.08 -1370.61,-184.08 -1414.08,-184.08 -1417.33,-180.83 -1439.68,-180.83 -1455.58,-180.83 -1470.55,-180.83 -1475.02,-185.3 -1475.02,-188.26 -1477.11,-190.36 -1480.07,-190.36 -1501.87,-190.36 -1503.96,-188.26 -1504.73,-188.26 -1504.73,-187.49 -1506.28,-185.95 -1506.28,-143.38 -1506.28,-140.42 -1503.18,-137.32 -1500.22,-137.32 -1499.68,-136.78 -1499.14,-137.32 -1477.34,-137.32 -1472.93,-141.73
GROUND RETURN:
  pour cut-out: -1467.9,-146.76 -1435.9,-146.76 -1415.9,-146.76 -1414.08,-142.58 -1357.64,-142.58 -1340.94,-125.89 -1337.43,-125.89 -1314.23,-125.89 -1310.71,-125.89 -1299.69,-136.9 -1291.82,-148.3 -1289.33,-150.78 -1289.33,-177.5 -1291.82,-179.99 -1310.71,-198.88 -1314.23,-198.88 -1337.43,-198.88 -1340.94,-198.88 -1355.74,-184.08 -1370.61,-184.08 -1414.08,-184.08 -1417.33,-180.83 -1439.68,-180.83 -1455.58,-180.83 -1470.55,-180.83 -1475.02,-185.3 -1475.02,-188.26 -1477.11,-190.36 -1480.07,-190.36 -1501.87,-190.36 -1503.96,-188.26 -1504.73,-188.26 -1504.73,-187.49 -1506.28,-185.95 -1506.28,-143.38 -1506.28,-140.42 -1503.18,-137.32 -1500.22,-137.32 -1499.68,-136.78 -1499.14,-137.32 -1477.34,-137.32 -1472.93,-141.73
Bottom Layer:
  pour cut-out: -1467.9,-146.76 -1435.9,-146.76 -1415.9,-146.76 -1414.08,-142.58 -1357.64,-142.58 -1340.94,-125.89 -1337.43,-125.89 -1314.23,-125.89 -1310.71,-125.89 -1299.69,-136.9 -1291.82,-148.3 -1289.33,-150.78 -1289.33,-177.5 -1291.82,-179.99 -1310.71,-198.88 -1314.23,-198.88 -1337.43,-198.88 -1340.94,-198.88 -1355.74,-184.08 -1370.61,-184.08 -1414.08,-184.08 -1417.33,-180.83 -1439.68,-180.83 -1455.58,-180.83 -1470.55,-180.83 -1475.02,-185.3 -1475.02,-188.26 -1477.11,-190.36 -1480.07,-190.36 -1501.87,-190.36 -1503.96,-188.26 -1504.73,-188.26 -1504.73,-187.49 -1506.28,-185.95 -1506.28,-143.38 -1506.28,-140.42 -1503.18,-137.32 -1500.22,-137.32 -1499.68,-136.78 -1499.14,-137.32 -1477.34,-137.32 -1472.93,-141.73

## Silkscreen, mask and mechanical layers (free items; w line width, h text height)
Top Overlay:
  lines w5: -1222.62,-312.82 ccw(c-191.92,-112.47) -1101.24,-637.47 ; -1222.62,87.88 cw(c-191.92,-112.47) -1165.46,280.87 ; -1135.65,347.82 cw(c-191.92,-112.47) 410.34,747.64
  lines w10: -1661.19,-112.46 -185,-112.47 479.64,856.04 ; -1221.93,-703.41 -200.02,-113.41 ; -1144.34,27.3 -1661.19,27.3 -1661.19,-252.22 -1139.41,-252.23 ; -1134.07,-491.29 -1581.67,-749.71 -1441.9,-991.79 -990.02,-730.9 ; 217.38,725.16 557.13,1210.37 786.1,1050.04 446.35,564.83
Bottom Overlay:
  text "GND" at -409.19,1505.75 h45
  text "RST" at -11.77,1505.75 h45
  text "TXD" at 85.12,1506.25 h45
  text "RXD" at 187.92,1506.25 h45
  text "5V" at 372.45,1506.25 h45
  text "GND" at 490.61,1505.75 h45
  text "SWDIO" at -164.39,1406.63 h45 r270
  text "BSL_invoke" at -356.17,1399.87 h30 r270
  text "SWCLK" at -265.56,1399.27 h45 r270
  text "'.PRJ_Number'" at 549,-909 h60
Top Paste:
  text ".Layer_Name" at -1161.91,-2932.68 h60
Drill Guide:
  text ".Layer_Name" at -1161.91,-2932.68 h60
M1 Board Outline:
  circle w10: c0,0 r1850
  text ".Layer_Name" at -1161.91,-2932.68 h60
M2 Board Dimensions:
  rectangle: -2084.02,-2315.19 -1959.02,-2190.19
  rectangle: -1959.02,-2440.19 -1584.02,-2315.19
  lines w5: -1101.24,-637.47 cw(c-191.92,-112.47) 410.34,747.64
  lines w7: -2084.02,-2315.19 -1084.02,-2315.19 ; -1959.02,-2440.19 -1959.02,-2190.19 ; -1834.02,-2440.19 -1834.02,-2190.19 ; -1584.02,-2440.19 -1584.02,-2190.19 ; -1334.02,-2440.19 -1334.02,-2190.19 ; -2084.02,-2440.19 -1084.02,-2440.19 -1084.02,-2190.19 -2084.02,-2190.19 -2084.02,-2440.19
  text ".Layer_Name" at -1161.91,-2932.68 h60
M3 3D STEP Top:
  text ".Layer_Name" at -1161.91,-2932.68 h60
M4 3D STEP Bottom:
  text ".Layer_Name" at -1161.91,-2932.68 h60
M5 Assembly Top:
  lines w10: -2030.91,-3004.36 4569.09,-3004.36 ; -2030.91,-2801.02 4571.09,-2801.02 ; -2030.91,-2597.69 -2030.91,-3207.69 1974.09,-3207.69 4571.09,-3207.69 4571.09,-2597.69 -2030.41,-2597.69 -2030.41,-3207.69 -454.91,-3207.69 ; 434.09,-3207.69 434.09,-2597.69 ; 1701.09,-2801.02 1701.09,-2597.69 ; 2541.09,-2801.02 2541.09,-2597.69 ; 3163.09,-3214.19 3163.09,-3011.36
  text "PCB VIEWED FROM TOP SIDE" at -1967.41,-2729.86 h60
  text "BOARD #:" at 509.09,-2729.86 h60
  text ".PRJ_Number" at 1054.59,-2729.86 h60
  text "REV:" at 1899.09,-2729.86 h60
  text ".PCB_Rev" at 2190.59,-2729.86 h60
  text "SVN REV:" at 2737.09,-2729.86 h60
  text ".VersionControl_RevNumber" at 3243.09,-2729.86 h60
  text "TID #:" at 509.09,-2933.19 h60
  text ".TID" at 1054.59,-2933.19 h60
  text "PLOT NAME =" at -1967.41,-3138.53 h60
  text ".plot_File_Name" at -1161.91,-3138.53 h60
  text "GENERATED    :" at 511.09,-3138.53 h60
  text ".Print_Date" at 1380.59,-3138.53 h60
  text ".Print_Time" at 2109.59,-3138.53 h60
  text "TEXAS INSTRUMENTS" at 3374.09,-3138.53 h60
M6 Assembly Bottom:
  lines w10: -2031.41,-2801.52 4570.59,-2801.52 ; -2029.41,-3004.86 4570.59,-3004.86 ; -623.41,-3214.69 -623.41,-3011.86 ; -1.41,-2801.52 -1.41,-2598.19 ; 838.59,-2801.52 838.59,-2598.19 ; 2105.59,-3208.19 2105.59,-2598.19 ; 2994.59,-3208.19 4570.09,-3208.19 4570.09,-2598.19 -2031.41,-2598.19 -2031.41,-3208.19 565.59,-3208.19 4570.59,-3208.19 4570.59,-2598.19
  text "COMPONENTS MARKED 'DNP' SHOULD NOT BE POPULATED." at 4363.09,-2392.19 h27.5
  text ".VariantName" at 3319.09,-2508.19 h27.5
  text "ASSEMBLY VARIANT:" at 4358.09,-2508.19 h27.5
  text ".VersionControl_RevNumber" at -703.41,-2730.36 h60
  text "SVN REV:" at -197.41,-2730.36 h60
  text ".PCB_Rev" at 349.09,-2730.36 h60
  text "REV:" at 640.59,-2730.36 h60
  text ".PRJ_Number" at 1485.09,-2730.36 h60
  text "BOARD #:" at 2030.59,-2730.36 h60
  text "PCB VIEWED FROM BOTTOM SIDE" at 4507.09,-2730.36 h60
  text ".TID" at 1485.09,-2933.69 h60
  text "TID #:" at 2030.59,-2933.69 h60
  text "TEXAS INSTRUMENTS" at -834.41,-3139.03 h60
  text ".Print_Time" at 430.09,-3139.03 h60
  text ".Print_Date" at 1159.09,-3139.03 h60
  text "GENERATED    :" at 2028.59,-3139.03 h60
  text ".plot_File_Name" at 3701.59,-3139.03 h60
  text "PLOT NAME =" at 4507.09,-3139.03 h60
M9 Title Sheet:
  drawing of 57 lines, arcs and shapes, not listed
  text "1" at -999.07,5962.31 h70
  text "2" at 1496.59,5962.31 h70
  text "3" at 3985.94,5962.31 h70
  text "4" at 6492.6,5962.31 h70
  text "5" at 8991.59,5962.31 h70
  text "6" at 11496.59,5962.31 h70
  text "A" at -2155.41,4819.31 h70
  text "A" at 12644.59,4819.31 h70
  text "B" at -2155.41,2439.31 h70
  text "B" at 12644.59,2439.31 h70
  text "C" at -2155.41,64.31 h70
  text "C" at 12644.59,64.31 h70
  text "PROJECT TITLE:" at 9604.59,-1796.69 h45
  text ".PRJ_Title" at 9654.59,-1930.02 h70
  text "DESIGNED FOR:" at 9604.59,-2097.69 h45
  text ".PRJ_Customer" at 9654.59,-2237.69 h70
  text "D" at -2155.41,-2305.69 h70
  text "D" at 12644.59,-2305.69 h70
  text "FILE NAME:" at 9604.59,-2397.69 h45
  text ".PCB_File_Name_No_Path" at 9654.59,-2517.69 h70
  text "Texas Instruments (TI) and/or its licensors do not warrant the accuracy or completeness of this specification" at 4635.09,-2679.53 h45
  text "ENGINEER:" at 9604.59,-2687.69 h45
  text "LAYOUT BY:" at 11109.59,-2687.69 h45
  text "or any information contained therein. TI and/or its licensors do not warrant that this design will meet" at 4590.11,-2792.19 h45
  text ".PRJ_Engineer" at 9654.59,-2842.68 h70
  text ".PCB_Layout" at 11160.09,-2842.68 h70
  text "the specifications, will be suitable for your application or fit for any particular purpose, or will operate in" at 4590.11,-2904.86 h45
  text ".Layer_Name" at -1161.91,-2932.68 h60
  text "ALTIUM DESIGNER VERSION:" at 11109.59,-2997.69 h45
  text "an implementation. TI and/or its licensors do not warrant that the design is production worthy. You should" at 4590.11,-3017.52 h45
  text "completely validate and test your design implementation to confirm the system functionality for your application." at 4635.09,-3130.19 h45
  text ".print_Scale" at 9654.59,-3131.02 h70
  text ".Application_BuildNumber" at 11160.09,-3131.02 h70
  text "1" at -999.07,-3337.69 h70
  text "2" at 1496.59,-3337.69 h70
  text "3" at 3985.94,-3337.69 h70
  text "4" at 6492.6,-3337.69 h70
  text "5" at 8991.59,-3337.69 h70
  text "6" at 11496.59,-3337.69 h70
M10 Fab Notes:
  drawing of 189 lines, arcs and shapes, not listed
  text "DESIGN INFORMATION" at 10643.11,4281.98 h60
  text "MIN. TRACK WIDTH:" at 9998.55,4149.86 h60
  text "8" at 11094.8,4149.86 h60
  text "MIL" at 11249.55,4149.86 h60
  text "MIN. CLEARANCE:" at 9998.55,4025.73 h60
  text "0.2" at 11034.8,4025.74 h60
  text "mm" at 11249.55,4025.73 h60
  text "MIN. VIA PAD SIZE:" at 9998.55,3901.61 h60
  text "20" at 11064.81,3901.61 h60
  text "MIL" at 11249.55,3901.61 h60
  text "0.05mm (2MIL)" at 10693.55,3771.71 h60
  text "MINIMUM ANNULAR RING" at 9669.32,3763.48 h60
  text "EXTERNAL" at 11401.55,3763.48 h60
  text "PER" at 9869.32,3653.36 h60
  text "IPC-D-275 CLASS 2 LEVEL C" at 10089.32,3653.35 h60
  text "MIL, HOLES" at 11577.55,3552.88 h60
  text "+/-" at 11185.09,3544.29 h60
  text "+/-" at 12039.09,3544.29 h60
  text "REGISTRATION TOLERANCES:" at 9669.32,3543.23 h60
  text "METAL" at 10869.09,3543.23 h60
  text "5" at 11445.3,3543.23 h60
  text "3" at 12278.3,3543.23 h60
  text "MIL" at 12394.55,3543.23 h60
  text "HOLE SIZE TOLERANCE (UNLESS OTHERWISE SPECIFIED):" at 9669.32,3444.91 h60
  text "+/-" at 12039.09,3442.04 h60
  text "3" at 12278.3,3440.98 h60
  text "MIL" at 12394.55,3440.98 h60
  text "MATERIAL:" at 9594.55,3303.33 h60
  text "FR-4 High Tg" at 10581,3174.81 h60
  text "X" at 10436.56,3166.82 h60
  text "FR-408" at 10015.56,3162.3 h60
  text "OTHER" at 11503.55,3162.3 h60
  text "62 MIL (1.6mm) +/-10%" at 10335.66,3019.27 h60
  text "X" at 10215.56,3016.82 h60
  text "THICKNESS:" at 9669.32,3011.05 h60
  text "OTHER" at 11620.55,3011.05 h60
  text "TOLERANCE:" at 9669.32,2872.73 h60
  text "X" at 10517.56,2872.73 h60
  text "ANSI IPC-6012 TYPE 3 CLASS 2" at 10695.57,2872.73 h60
  text "OTHER +/-" at 10695.55,2728.54 h60
  text "BOW & TWIST:" at 9669.32,2583.35 h60
  text "X" at 10517.56,2583.35 h60
  text "ANSI IPC-6012 TYPE 3 CLASS 2" at 10695.57,2583.35 h60
  text "OTHER +/-" at 10695.55,2436.66 h60
  text "DRILLING:" at 9594.55,2306.04 h60
  text "NC_DRILL FILES" at 11355.55,2200.85 h60
  text "REFERENCE:" at 9669.32,2196.91 h60
  text "X" at 10326.56,2196.82 h60
  text "AS SHOWN" at 10504.55,2196.91 h60
  text "X" at 11227.56,2196.91 h60
  text "OTHER" at 11653.55,2054.66 h60
  text "PTH COPPER THICKNESS:" at 9669,2051.13 h60
  text "X" at 10808.24,2051.13 h60
  text "20-30 um" at 10936.23,2051.13 h60
  text "BOARD FINISH:" at 9594.55,1903.54 h60
  text "SILKSCREEN:" at 9749.78,1793.41 h60
  text "X" at 10707.56,1793.41 h60
  text "TOP" at 10824.55,1793.41 h60
  text "X" at 11217.56,1793.41 h60
  text "BOTTOM" at 11335.55,1793.41 h60
  text "SILKSCREEN COLOR:" at 9749.78,1638.22 h60
  text "X" at 10706.56,1638.22 h60
  text "WHITE" at 10824.55,1638.22 h60
  text "OTHER" at 11335.55,1638.22 h60
  text "GREEN" at 10955.55,1494.77 h60
  text "X" at 11436.09,1494.77 h60
  text "OTHER" at 11573.55,1494.77 h60
  text "BLACK" at 11970.55,1489.77 h60
  text "SOLDER RESIST COLOR:" at 9749.78,1487.91 h60
  text "X" at 10837.56,1340.52 h60
  text "MATTE" at 10955.55,1340.52 h60
  text "SEMI-GLOSS" at 11573.09,1339.88 h60
  text "IMMERSION GOLD (ENIG)" at 10655.55,1167.75 h60
  text "ENEPIG" at 11993.09,1160.53 h60
  text "SURFACE FINISH:" at 9594.55,1159.53 h60
  text "X" at 10477.56,1159.53 h60
  text "IMM. TIN/SILVER OR EQUIV" at 9924.09,1022.21 h60
  text "OTHER" at 11355.55,1018.28 h60
  text "ARRAY/PANEL:" at 9594.55,862.9 h60
  text "CUT AND TRIM PER M1 BOARD OUTLINE" at 10655.55,854.68 h60
  text "N.C. ROUTE" at 10655.55,718.71 h60
  text "X" at 11343.56,718.71 h60
  text "V. SCORE" at 11521.55,718.71 h60
  text "CERTIFICATION:" at 9594.55,589.58 h60
  text "MATERIALS AND WORKMANSHIP FOR ALL PCBS" at 10319.55,589.58 h60
  text "TO MEET OR EXCEED THE REQUIREMENTS OF:" at 10319.55,495.52 h60
  text "X" at 9957.06,366.89 h60
  text "ANSI IPC-A-600F CLASS ->" at 10085.06,366.89 h60
  text "X" at 11733.06,366.89 h60
  text "2" at 11843.06,366.89 h60
  text "1" at 11528.06,365.39 h60
  text "3" at 12197.06,365.39 h60
  text "X" at 10769.06,219.2 h60
  text "RoHS" at 10897.06,219.2 h60
  text "OTHER" at 11541.46,219.2 h60
  text "PER ORDER" at 11938.52,219.2 h60
  text "ALL BOARDS MUST MEET OR EXCEED UL94-V0 REQUIREMENTS." at 9622.09,65.38 h60
  text "PCB MUST BEAR THE UL94V-0 UL REGISTERED MATERIAL ID NUMBER" at 9622.09,-50.69 h60
  text "ADDITIONAL REQUIREMENTS:" at 9594.55,-220.11 h60
  text "MICROSECTION:" at 9669.32,-327.24 h60
  text "YES" at 10575.06,-327.24 h60
  text "REQUIRED" at 11436.55,-471.57 h60
  text "BARE BOARD ELEC. TEST:" at 9669.32,-474.43 h60
  text "NONE" at 10975.06,-474.43 h60
  text "X" at 11318.56,-474.43 h60
  text "PER ORDER" at 12028.55,-474.43 h60
  text "XX MIL VIAS REQUIRE NON-CONDUCTIVE FILL AND PLANARIZE" at 9837.47,-679.37 h59
  text "XX MIL VIAS REQUIRE CONDUCTIVE FILL AND PLANARIZE" at 9845.47,-783.35 h60
  text "OUTER XX MIL TRACES REQUIRE 50 OHM SINGLE-ENDED IMPEDANCE" at 9844.49,-946.73 h58
  text "LAYER 2 & 3 (INNER LAYERS) XX MIL WIDE, XX MIL SPACE / TRACES REQUIRE 100 OHM DIFFERENTIAL IMPEDANCE" at 9836.49,-1182.45 h60
  text ".Layer_Name" at -1161.91,-2932.68 h60
M11 Gerber Information:
  lines w10: -2030.91,-3004.36 4569.09,-3004.36 ; -2030.91,-2801.02 4571.09,-2801.02 ; -2030.91,-2597.69 -2030.91,-3207.69 1974.09,-3207.69 4571.09,-3207.69 4571.09,-2597.69 -2030.41,-2597.69 -2030.41,-3207.69 -454.91,-3207.69 ; 434.09,-3207.69 434.09,-2597.69 ; 1701.09,-2801.02 1701.09,-2597.69 ; 2541.09,-2801.02 2541.09,-2597.69 ; 3163.09,-3214.19 3163.09,-3011.36
  text "ALL ARTWORK VIEWED FROM TOP SIDE" at -1967.41,-2729.86 h60
  text "BOARD #:" at 509.09,-2729.86 h60
  text ".PRJ_Number" at 1054.59,-2729.86 h60
  text "REV:" at 1899.09,-2729.86 h60
  text ".PCB_Rev" at 2190.59,-2729.86 h60
  text "SVN REV:" at 2737.09,-2729.86 h60
  text ".VersionControl_RevNumber" at 3243.09,-2729.86 h60
  text "LAYER NAME =" at -1967.41,-2932.68 h60
  text "TID #:" at 509.09,-2933.19 h60
  text ".TID" at 1054.59,-2933.19 h60
  text "PLOT NAME =" at -1967.41,-3138.53 h60
  text ".plot_File_Name" at -1161.91,-3138.53 h60
  text "GENERATED    :" at 511.09,-3138.53 h60
  text ".Print_Date" at 1380.59,-3138.53 h60
  text ".Print_Time" at 2109.59,-3138.53 h60
  text "TEXAS INSTRUMENTS" at 3374.09,-3138.53 h60
M12 Stackup:
  text ".Layer_Name" at -1161.91,-2932.68 h60
M13 Component Bodies Top:
  text ".Layer_Name" at -1161.91,-2932.68 h60
Drill Drawing:
  circle w10: c3591.47,951.71 r15.28
  circle w10: c3591.47,745.46 r9.17
  circle w10: c3591.47,745.46 r15.28
  lines w10: 3576.19,669.07 3583.83,669.07 3591.47,661.43 3599.11,669.07 3606.75,669.07 3599.11,676.71 3606.75,684.35 3599.11,684.35 3591.47,691.99 3583.83,684.35 3576.19,684.35 3583.83,676.71 3576.19,669.07 ; 3576.19,798.93 3606.75,798.93 3606.75,829.49 3576.19,829.49 3576.19,798.93 ; 3576.19,867.68 3591.47,875.32 3606.75,867.68 3599.11,882.96 3606.75,898.24 3591.47,890.6 3576.19,898.24 3583.83,882.96 3576.19,867.68 ; 3576.19,1012.82 3583.83,1012.82 3583.83,1005.18 3599.11,1005.18 3599.11,1012.82 3606.75,1012.82 3606.75,1028.1 3599.11,1028.1 3599.11,1035.74 3583.83,1035.74 3583.83,1028.1 3576.19,1028.1 3576.19,1012.82 ; 3576.19,1104.49 3606.75,1104.49 3591.47,1073.93 3576.19,1104.49 ; 3576.19,1150.32 3583.83,1150.32 3591.47,1142.68 3599.11,1150.32 3606.75,1150.32 3599.11,1157.96 3606.75,1165.6 3599.11,1165.6 3591.47,1173.24 3583.83,1165.6 3576.19,1165.6 3583.83,1157.96 3576.19,1150.32 ; 3576.19,1211.43 3576.19,1219.07 3583.83,1226.71 3576.19,1234.35 3576.19,1241.99 3583.83,1241.99 3591.47,1234.35 3599.11,1241.99 3606.75,1241.99 3606.75,1234.35 3599.11,1226.71 3606.75,1219.07 3606.75,1211.43 3599.11,1211.43 3591.47,1219.07 3583.83,1211.43 3576.19,1211.43 ; 3576.19,1280.18 3576.19,1287.82 3583.83,1295.46 3576.19,1303.1 3576.19,1310.74 3583.83,1310.74 3591.47,1303.1 3599.11,1310.74 3606.75,1310.74 3606.75,1303.1 3599.11,1295.46 3606.75,1287.82 3606.75,1280.18 3599.11,1280.18 3591.47,1287.82 3583.83,1280.18 3576.19,1280.18 ; 3576.19,1348.93 3606.75,1348.93 3606.75,1379.49 3576.19,1379.49 3576.19,1348.93 ; 3582.3,1153.38 3586.89,1153.38 3591.47,1148.8 3596.05,1153.38 3600.64,1153.38 3596.05,1157.96 3600.64,1162.55 3596.05,1162.55 3591.47,1167.13 3586.89,1162.55 3582.3,1162.55 3586.89,1157.96 3582.3,1153.38 ; 3582.3,1286.3 3582.3,1290.88 3586.89,1295.46 3582.3,1300.05 3582.3,1304.63 3586.89,1304.63 3591.47,1300.05 3596.05,1304.63 3600.64,1304.63 3600.64,1300.05 3596.05,1295.46 3600.64,1290.88 3600.64,1286.3 3596.05,1286.3 3591.47,1290.88 3586.89,1286.3 3582.3,1286.3 ; 3582.3,1355.05 3600.64,1355.05 3600.64,1373.38 3582.3,1373.38 3582.3,1355.05
  lines w12: 3547.09,640.81 6595.37,640.81 ; 3547.09,1397.06 6595.37,1397.06 ; 3816.91,572.06 3816.91,1465.81 ; 4126.59,572.06 4126.59,1465.81 ; 4760.65,572.06 4760.65,1465.81 ; 5009.85,572.06 5009.85,1465.81 ; 5363.51,572.06 5363.51,1465.81 ; 6061.63,572.06 6061.63,1465.81 ; 3547.09,572.06 6595.37,572.06 6595.37,1465.81 3547.09,1465.81 3547.09,572.06
  text "Symbol" at 3588.34,1417.68 h33
  text "Quantity" at 3837.54,1417.68 h33
  text "Finished Hole Size" at 4147.21,1417.68 h33
  text "Plated" at 4781.28,1417.68 h33
  text "Hole Type" at 5030.47,1417.68 h33
  text "Drill Layer Pair" at 5384.13,1417.68 h33
  text "Hole Tolerance" at 6082.26,1417.68 h33
  text "2" at 3837.54,1348.93 h27.5
  text "35.43mil (0.900mm)" at 4147.21,1348.93 h27.5
  text "NPTH" at 4781.28,1348.93 h27.5
  text "Round" at 5030.47,1348.93 h27.5
  text "Top Layer - Bottom Layer" at 5384.13,1348.93 h27.5
  text "4" at 3837.54,1280.18 h27.5
  text "118.11mil (3.000mm)" at 4147.21,1280.18 h27.5
  text "NPTH" at 4781.28,1280.18 h27.5
  text "Round" at 5030.47,1280.18 h27.5
  text "Top Layer - Bottom Layer" at 5384.13,1280.18 h27.5
  text "+/-0.00mil" at 6082.26,1280.18 h27.5
  text "2" at 3837.54,1211.43 h27.5
  text "129.92mil (3.300mm)" at 4147.21,1211.43 h27.5
  text "NPTH" at 4781.28,1211.43 h27.5
  text "Round" at 5030.47,1211.43 h27.5
  text "Top Layer - Bottom Layer" at 5384.13,1211.43 h27.5
  text "48" at 3837.54,1142.68 h27.5
  text "7.87mil (0.200mm)" at 4147.21,1142.68 h27.5
  text "PTH" at 4781.28,1142.68 h27.5
  text "Round" at 5030.47,1142.68 h27.5
  text "Top Layer - Bottom Layer" at 5384.13,1142.68 h27.5
  text "222" at 3837.54,1073.93 h27.5
  text "8.00mil (0.203mm)" at 4147.21,1073.93 h27.5
  text "PTH" at 4781.28,1073.93 h27.5
  text "Round" at 5030.47,1073.93 h27.5
  text "Top Layer - Bottom Layer" at 5384.13,1073.93 h27.5
  text "1" at 3837.54,1005.18 h27.5
  text "10.00mil (0.254mm)" at 4147.21,1005.18 h27.5
  text "PTH" at 4781.28,1005.18 h27.5
  text "Round" at 5030.47,1005.18 h27.5
  text "Top Layer - Bottom Layer" at 5384.13,1005.18 h27.5
  text "2" at 3837.54,936.43 h27.5
  text "39.37mil (1.000mm)" at 4147.21,936.43 h27.5
  text "PTH" at 4781.28,936.43 h27.5
  text "Round" at 5030.47,936.43 h27.5
  text "Top Layer - Bottom Layer" at 5384.13,936.43 h27.5
  text "10" at 3837.54,867.68 h27.5
  text "40.16mil (1.020mm)" at 4147.21,867.68 h27.5
  text "PTH" at 4781.28,867.68 h27.5
  text "Round" at 5030.47,867.68 h27.5
  text "Top Layer - Bottom Layer" at 5384.13,867.68 h27.5
  text "4" at 3837.54,798.93 h27.5
  text "43.31mil (1.100mm)" at 4147.21,798.93 h27.5
  text "PTH" at 4781.28,798.93 h27.5
  text "Round" at 5030.47,798.93 h27.5
  text "Top Layer - Bottom Layer" at 5384.13,798.93 h27.5
  text "16" at 3837.54,730.18 h27.5
  text "45.28mil (1.150mm)" at 4147.21,730.18 h27.5
  text "PTH" at 4781.28,730.18 h27.5
  text "Round" at 5030.47,730.18 h27.5
  text "Top Layer - Bottom Layer" at 5384.13,730.18 h27.5
  text "2" at 3837.54,661.43 h27.5
  text "78.74mil (2.000mm)" at 4147.21,661.43 h27.5
  text "PTH" at 4781.28,661.43 h27.5
  text "Round" at 5030.47,661.43 h27.5
  text "Top Layer - Bottom Layer" at 5384.13,661.43 h27.5
  text "313 Total" at 3837.54,592.68 h27.5
  text ".Layer_Name" at -1161.91,-2932.68 h60
M17 Embedded Cavity:
  text ".Layer_Name" at -1161.91,-2932.68 h60
M18 Embedded Assembly:
  text ".Layer_Name" at -1161.91,-2932.68 h60
M19 Embedded Keepout:
  text ".Layer_Name" at -1161.91,-2932.68 h60

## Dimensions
-2084.02,-2440.19 to -1084.02,-2440.19 on M2 Board Dimensions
